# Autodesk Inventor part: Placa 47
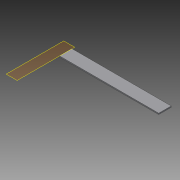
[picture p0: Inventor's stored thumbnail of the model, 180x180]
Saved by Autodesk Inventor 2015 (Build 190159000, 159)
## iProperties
Created: 2015-04
Part Number: Placa 47
Material: Generic
Document SubType Name: Modeling
Designer: suporte
Density: 1 g/cm^3
Appearance: Default
Author: suporte
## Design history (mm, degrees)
workplane "Work Plane1"
sketch "Sketch1"
  geometry: L1 (-50, -262.5)-(50, -262.5) reference; L2 (50, -262.5)-(50, 262.5) reference; L3 (50, 262.5)-(-50, 262.5) reference; L4 (-50, 262.5)-(-50, -262.5) reference; L5 (50, 137.5)-(1050, 137.5) reference; L6 (50, 137.5)-(1050, 137.5); L7 (1050, 137.5)-(1050, 262.5); L8 (1050, 262.5)-(50, 262.5); L9 (50, 262.5)-(50, 137.5); 1 further point
  constraints: 8 end point, 2 parallel, 1 horizontal, 1 perpendicular
extrude "Extrusion1" new body sketch "Sketch1" distance "d0" = 12.5; taper "d1" = 0 deg
body "Solid1"
node "Reference1"
node "Reference2"
